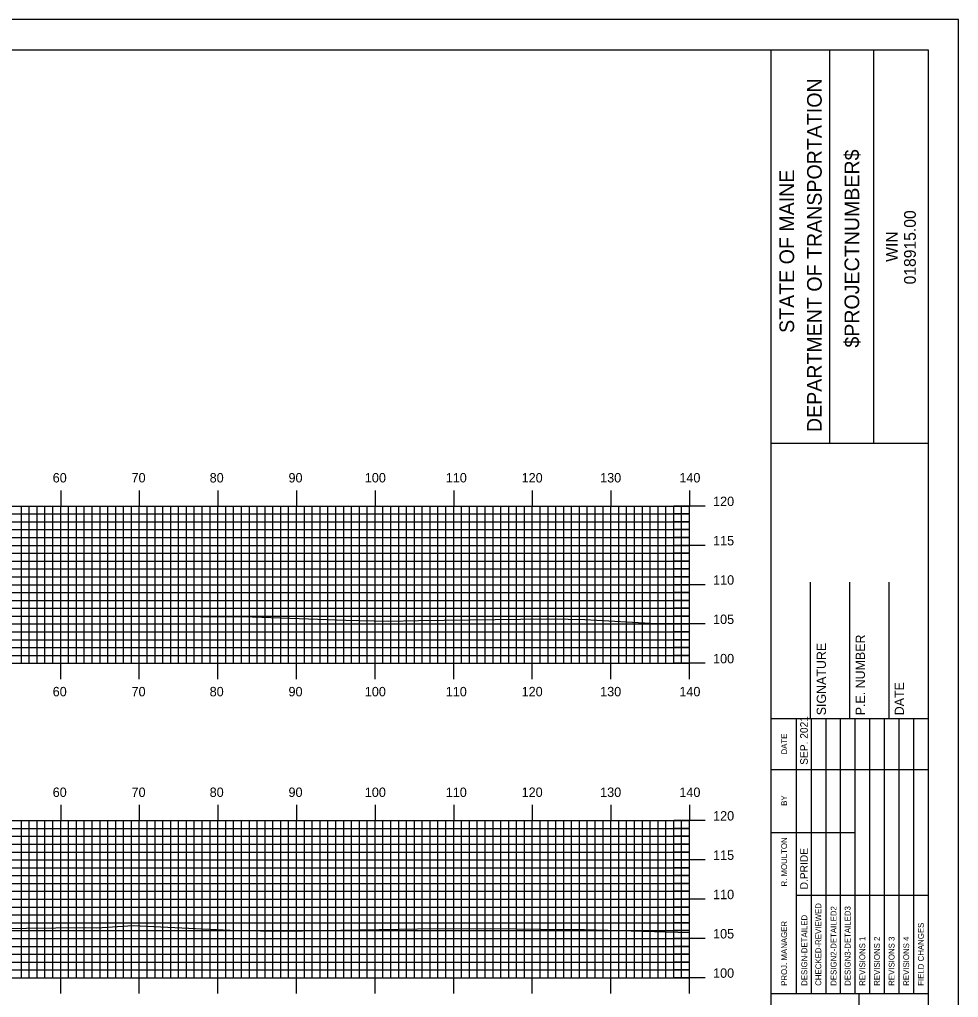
# Model space of a CAD drawing. Extents: x 1773203 to 1773546, y 442591 to 442811.
# Drawn here: x 1773423.4 to 1773542.8, y 442686.2 to 442810.5 of the extents above; entities that cross this region are included whole.
import ezdxf

# ---------------------------------------------------------------- set-up
doc = ezdxf.new("R2010")
doc.units = 0
for name, color, linetype in [('BORDER', 7, 'Continuous'), ('H_V ANNOTATION', 7, 'Continuous'), ('MAJOR', 7, 'Continuous'), ('MINOR', 7, 'Continuous'), ('PLOT BOUNDARY', 7, 'Continuous'), ('S_Roadway_Centerline', 7, 'Continuous')]:
    doc.layers.add(name, color=color, linetype=linetype)

msp = doc.modelspace()

# ---------------------------------------------------------------- linework, layer by layer
at = {"layer": 'BORDER'}
for p, q in [((1773519.03, 442596.67), (1773519.03, 442806.67)), ((1773526.49, 442756.66), (1773526.49, 442806.66)), ((1773532.08, 442756.66), (1773532.08, 442806.66)), ((1773519.03, 442756.65), (1773539.03, 442756.65)), ((1773524.03, 442721.67), (1773524.03, 442738.97)), ((1773529.03, 442721.67), (1773529.03, 442738.97)), ((1773534.03, 442721.67), (1773534.03, 442738.97)), ((1773519.03, 442721.67), (1773539.03, 442721.67)), ((1773519.03, 442686.67), (1773539.03, 442686.67)), ((1773530.21, 442616.67), (1773530.21, 442686.67))]:
    msp.add_line(p, q, dxfattribs=at)
msp.add_lwpolyline([(1773219.03, 442596.67), (1773539.03, 442596.67), (1773539.03, 442806.67), (1773219.03, 442806.67)], close=True, dxfattribs=at)
for points in [[(1773522.26, 442715.17), (1773522.26, 442721.67)], [(1773524.13, 442686.68), (1773524.13, 442721.67)], [(1773525.99, 442721.67), (1773525.99, 442686.68)], [(1773527.85, 442686.68), (1773527.85, 442721.67)], [(1773529.72, 442686.68), (1773529.72, 442721.67)], [(1773531.58, 442686.68), (1773531.58, 442721.67)], [(1773533.44, 442686.68), (1773533.44, 442721.67)], [(1773535.31, 442686.68), (1773535.31, 442721.67)], [(1773537.17, 442686.68), (1773537.17, 442721.67)], [(1773522.26, 442686.68), (1773522.26, 442720.26)], [(1773519.03, 442715.17), (1773539.03, 442715.17)], [(1773519.03, 442707.17), (1773522.26, 442707.17)], [(1773522.26, 442707.17), (1773529.72, 442707.17)], [(1773522.26, 442699.17), (1773539.03, 442699.17)]]:
    msp.add_lwpolyline(points, dxfattribs=at)
at = {"layer": 'MAJOR'}
for p, q in [((1773428.63, 442750.67), (1773428.63, 442748.67)), ((1773438.63, 442750.67), (1773438.63, 442748.67)), ((1773448.63, 442750.67), (1773448.63, 442748.67)), ((1773458.63, 442750.67), (1773458.63, 442748.67)), ((1773468.63, 442750.67), (1773468.63, 442748.67)), ((1773478.63, 442750.67), (1773478.63, 442748.67)), ((1773488.63, 442750.67), (1773488.63, 442748.67)), ((1773498.63, 442750.67), (1773498.63, 442748.67)), ((1773508.63, 442750.67), (1773508.63, 442748.67)), ((1773228.63, 442748.67), (1773508.63, 442748.67)), ((1773228.63, 442748.67), (1773508.63, 442748.67)), ((1773428.63, 442728.67), (1773428.63, 442748.67)), ((1773438.63, 442728.67), (1773438.63, 442748.67)), ((1773448.63, 442728.67), (1773448.63, 442748.67)), ((1773458.63, 442728.67), (1773458.63, 442748.67)), ((1773468.63, 442728.67), (1773468.63, 442748.67)), ((1773478.63, 442728.67), (1773478.63, 442748.67)), ((1773488.63, 442728.67), (1773488.63, 442748.67)), ((1773498.63, 442728.67), (1773498.63, 442748.67)), ((1773510.64, 442748.67), (1773506.63, 442748.67)), ((1773508.63, 442728.67), (1773508.63, 442748.67)), ((1773508.63, 442728.67), (1773508.63, 442748.67)), ((1773228.63, 442743.67), (1773508.63, 442743.67)), ((1773510.64, 442743.67), (1773506.63, 442743.67)), ((1773228.63, 442738.67), (1773508.63, 442738.67)), ((1773510.64, 442738.67), (1773506.63, 442738.67)), ((1773228.63, 442733.67), (1773508.63, 442733.67)), ((1773510.64, 442733.67), (1773506.63, 442733.67)), ((1773228.63, 442728.67), (1773508.63, 442728.67)), ((1773228.63, 442728.67), (1773508.63, 442728.67)), ((1773428.63, 442726.66), (1773428.63, 442728.67)), ((1773438.63, 442726.66), (1773438.63, 442728.67)), ((1773448.63, 442726.66), (1773448.63, 442728.67)), ((1773458.63, 442726.66), (1773458.63, 442728.67)), ((1773468.63, 442726.66), (1773468.63, 442728.67)), ((1773478.63, 442726.66), (1773478.63, 442728.67)), ((1773488.63, 442726.66), (1773488.63, 442728.67)), ((1773498.63, 442726.66), (1773498.63, 442728.67)), ((1773510.64, 442728.67), (1773506.63, 442728.67)), ((1773508.63, 442726.66), (1773508.63, 442728.67)), ((1773428.63, 442710.67), (1773428.63, 442708.67)), ((1773438.63, 442710.67), (1773438.63, 442708.67)), ((1773448.63, 442710.67), (1773448.63, 442708.67)), ((1773458.63, 442710.67), (1773458.63, 442708.67)), ((1773468.63, 442710.67), (1773468.63, 442708.67)), ((1773478.63, 442710.67), (1773478.63, 442708.67)), ((1773488.63, 442710.67), (1773488.63, 442708.67)), ((1773498.63, 442710.67), (1773498.63, 442708.67)), ((1773508.63, 442710.67), (1773508.63, 442708.67)), ((1773228.63, 442708.67), (1773508.63, 442708.67)), ((1773228.63, 442708.67), (1773508.63, 442708.67)), ((1773428.63, 442688.67), (1773428.63, 442708.67)), ((1773438.63, 442688.67), (1773438.63, 442708.67)), ((1773448.63, 442688.67), (1773448.63, 442708.67)), ((1773458.63, 442688.67), (1773458.63, 442708.67)), ((1773468.63, 442688.67), (1773468.63, 442708.67)), ((1773478.63, 442688.67), (1773478.63, 442708.67)), ((1773488.63, 442688.67), (1773488.63, 442708.67)), ((1773498.63, 442688.67), (1773498.63, 442708.67)), ((1773510.64, 442708.67), (1773506.63, 442708.67)), ((1773508.63, 442688.67), (1773508.63, 442708.67)), ((1773508.63, 442688.67), (1773508.63, 442708.67)), ((1773228.63, 442703.67), (1773508.63, 442703.67)), ((1773510.64, 442703.67), (1773506.63, 442703.67)), ((1773228.63, 442698.67), (1773508.63, 442698.67)), ((1773510.64, 442698.67), (1773506.63, 442698.67)), ((1773228.63, 442693.67), (1773508.63, 442693.67)), ((1773510.64, 442693.67), (1773506.63, 442693.67)), ((1773228.63, 442688.67), (1773508.63, 442688.67)), ((1773228.63, 442688.67), (1773508.63, 442688.67)), ((1773428.63, 442686.66), (1773428.63, 442688.67)), ((1773438.63, 442686.66), (1773438.63, 442688.67)), ((1773448.63, 442686.66), (1773448.63, 442688.67)), ((1773458.63, 442686.66), (1773458.63, 442688.67)), ((1773468.63, 442686.66), (1773468.63, 442688.67)), ((1773478.63, 442686.66), (1773478.63, 442688.67)), ((1773488.63, 442686.66), (1773488.63, 442688.67)), ((1773498.63, 442686.66), (1773498.63, 442688.67)), ((1773510.64, 442688.67), (1773506.63, 442688.67)), ((1773508.63, 442686.66), (1773508.63, 442688.67))]:
    msp.add_line(p, q, dxfattribs=at)
at = {"layer": 'MINOR'}
for p, q in [((1773423.63, 442728.67), (1773423.63, 442748.67)), ((1773424.63, 442728.67), (1773424.63, 442748.67)), ((1773425.63, 442728.67), (1773425.63, 442748.67)), ((1773426.63, 442728.67), (1773426.63, 442748.67)), ((1773427.63, 442728.67), (1773427.63, 442748.67)), ((1773429.63, 442728.67), (1773429.63, 442748.67)), ((1773430.63, 442728.67), (1773430.63, 442748.67)), ((1773431.63, 442728.67), (1773431.63, 442748.67)), ((1773432.63, 442728.67), (1773432.63, 442748.67)), ((1773433.63, 442728.67), (1773433.63, 442748.67)), ((1773434.63, 442728.67), (1773434.63, 442748.67)), ((1773435.63, 442728.67), (1773435.63, 442748.67)), ((1773436.63, 442728.67), (1773436.63, 442748.67)), ((1773437.63, 442728.67), (1773437.63, 442748.67)), ((1773439.63, 442728.67), (1773439.63, 442748.67)), ((1773440.63, 442728.67), (1773440.63, 442748.67)), ((1773441.63, 442728.67), (1773441.63, 442748.67)), ((1773442.63, 442728.67), (1773442.63, 442748.67)), ((1773443.63, 442728.67), (1773443.63, 442748.67)), ((1773444.63, 442728.67), (1773444.63, 442748.67)), ((1773445.63, 442728.67), (1773445.63, 442748.67)), ((1773446.63, 442728.67), (1773446.63, 442748.67)), ((1773447.63, 442728.67), (1773447.63, 442748.67)), ((1773449.63, 442728.67), (1773449.63, 442748.67)), ((1773450.63, 442728.67), (1773450.63, 442748.67)), ((1773451.63, 442728.67), (1773451.63, 442748.67)), ((1773452.63, 442728.67), (1773452.63, 442748.67)), ((1773453.63, 442728.67), (1773453.63, 442748.67)), ((1773454.63, 442728.67), (1773454.63, 442748.67)), ((1773455.63, 442728.67), (1773455.63, 442748.67)), ((1773456.63, 442728.67), (1773456.63, 442748.67)), ((1773457.63, 442728.67), (1773457.63, 442748.67)), ((1773459.63, 442728.67), (1773459.63, 442748.67)), ((1773460.63, 442728.67), (1773460.63, 442748.67)), ((1773461.63, 442728.67), (1773461.63, 442748.67)), ((1773462.63, 442728.67), (1773462.63, 442748.67)), ((1773463.63, 442728.67), (1773463.63, 442748.67)), ((1773464.63, 442728.67), (1773464.63, 442748.67)), ((1773465.63, 442728.67), (1773465.63, 442748.67)), ((1773466.63, 442728.67), (1773466.63, 442748.67)), ((1773467.63, 442728.67), (1773467.63, 442748.67)), ((1773469.63, 442728.67), (1773469.63, 442748.67)), ((1773470.63, 442728.67), (1773470.63, 442748.67)), ((1773471.63, 442728.67), (1773471.63, 442748.67)), ((1773472.63, 442728.67), (1773472.63, 442748.67)), ((1773473.63, 442728.67), (1773473.63, 442748.67)), ((1773474.63, 442728.67), (1773474.63, 442748.67)), ((1773475.63, 442728.67), (1773475.63, 442748.67)), ((1773476.63, 442728.67), (1773476.63, 442748.67)), ((1773477.63, 442728.67), (1773477.63, 442748.67)), ((1773479.63, 442728.67), (1773479.63, 442748.67)), ((1773480.63, 442728.67), (1773480.63, 442748.67)), ((1773481.63, 442728.67), (1773481.63, 442748.67)), ((1773482.63, 442728.67), (1773482.63, 442748.67)), ((1773483.63, 442728.67), (1773483.63, 442748.67)), ((1773484.63, 442728.67), (1773484.63, 442748.67)), ((1773485.63, 442728.67), (1773485.63, 442748.67)), ((1773486.63, 442728.67), (1773486.63, 442748.67)), ((1773487.63, 442728.67), (1773487.63, 442748.67)), ((1773489.63, 442728.67), (1773489.63, 442748.67)), ((1773490.63, 442728.67), (1773490.63, 442748.67)), ((1773491.63, 442728.67), (1773491.63, 442748.67)), ((1773492.63, 442728.67), (1773492.63, 442748.67)), ((1773493.63, 442728.67), (1773493.63, 442748.67)), ((1773494.63, 442728.67), (1773494.63, 442748.67)), ((1773495.63, 442728.67), (1773495.63, 442748.67)), ((1773496.63, 442728.67), (1773496.63, 442748.67)), ((1773497.63, 442728.67), (1773497.63, 442748.67)), ((1773499.63, 442728.67), (1773499.63, 442748.67)), ((1773500.63, 442728.67), (1773500.63, 442748.67)), ((1773501.63, 442728.67), (1773501.63, 442748.67)), ((1773502.63, 442728.67), (1773502.63, 442748.67)), ((1773503.63, 442728.67), (1773503.63, 442748.67)), ((1773504.63, 442728.67), (1773504.63, 442748.67)), ((1773505.63, 442728.67), (1773505.63, 442748.67)), ((1773506.63, 442728.67), (1773506.63, 442748.67)), ((1773507.63, 442728.67), (1773507.63, 442748.67)), ((1773228.63, 442747.67), (1773508.63, 442747.67)), ((1773508.63, 442747.67), (1773506.63, 442747.67)), ((1773228.63, 442746.67), (1773508.63, 442746.67)), ((1773228.63, 442745.67), (1773508.63, 442745.67)), ((1773508.63, 442746.67), (1773506.63, 442746.67)), ((1773508.63, 442745.67), (1773506.63, 442745.67)), ((1773228.63, 442744.67), (1773508.63, 442744.67)), ((1773508.63, 442744.67), (1773506.63, 442744.67)), ((1773228.63, 442742.67), (1773508.63, 442742.67)), ((1773508.63, 442742.67), (1773506.63, 442742.67)), ((1773228.63, 442741.67), (1773508.63, 442741.67)), ((1773228.63, 442740.67), (1773508.63, 442740.67)), ((1773508.63, 442741.67), (1773506.63, 442741.67)), ((1773508.63, 442740.67), (1773506.63, 442740.67)), ((1773228.63, 442739.67), (1773508.63, 442739.67)), ((1773508.63, 442739.67), (1773506.63, 442739.67)), ((1773228.63, 442737.67), (1773508.63, 442737.67)), ((1773508.63, 442737.67), (1773506.63, 442737.67)), ((1773228.63, 442736.67), (1773508.63, 442736.67)), ((1773228.63, 442735.67), (1773508.63, 442735.67)), ((1773508.63, 442736.67), (1773506.63, 442736.67)), ((1773508.63, 442735.67), (1773506.63, 442735.67)), ((1773228.63, 442734.67), (1773508.63, 442734.67)), ((1773508.63, 442734.67), (1773506.63, 442734.67)), ((1773228.63, 442732.67), (1773508.63, 442732.67)), ((1773508.63, 442732.67), (1773506.63, 442732.67)), ((1773228.63, 442731.67), (1773508.63, 442731.67)), ((1773228.63, 442730.67), (1773508.63, 442730.67)), ((1773508.63, 442731.67), (1773506.63, 442731.67)), ((1773508.63, 442730.67), (1773506.63, 442730.67)), ((1773228.63, 442729.67), (1773508.63, 442729.67)), ((1773508.63, 442729.67), (1773506.63, 442729.67)), ((1773423.63, 442688.67), (1773423.63, 442708.67)), ((1773424.63, 442688.67), (1773424.63, 442708.67)), ((1773425.63, 442688.67), (1773425.63, 442708.67)), ((1773426.63, 442688.67), (1773426.63, 442708.67)), ((1773427.63, 442688.67), (1773427.63, 442708.67)), ((1773429.63, 442688.67), (1773429.63, 442708.67)), ((1773430.63, 442688.67), (1773430.63, 442708.67)), ((1773431.63, 442688.67), (1773431.63, 442708.67)), ((1773432.63, 442688.67), (1773432.63, 442708.67)), ((1773433.63, 442688.67), (1773433.63, 442708.67)), ((1773434.63, 442688.67), (1773434.63, 442708.67)), ((1773435.63, 442688.67), (1773435.63, 442708.67)), ((1773436.63, 442688.67), (1773436.63, 442708.67)), ((1773437.63, 442688.67), (1773437.63, 442708.67)), ((1773439.63, 442688.67), (1773439.63, 442708.67)), ((1773440.63, 442688.67), (1773440.63, 442708.67)), ((1773441.63, 442688.67), (1773441.63, 442708.67)), ((1773442.63, 442688.67), (1773442.63, 442708.67)), ((1773443.63, 442688.67), (1773443.63, 442708.67)), ((1773444.63, 442688.67), (1773444.63, 442708.67)), ((1773445.63, 442688.67), (1773445.63, 442708.67)), ((1773446.63, 442688.67), (1773446.63, 442708.67)), ((1773447.63, 442688.67), (1773447.63, 442708.67)), ((1773449.63, 442688.67), (1773449.63, 442708.67)), ((1773450.63, 442688.67), (1773450.63, 442708.67)), ((1773451.63, 442688.67), (1773451.63, 442708.67)), ((1773452.63, 442688.67), (1773452.63, 442708.67)), ((1773453.63, 442688.67), (1773453.63, 442708.67)), ((1773454.63, 442688.67), (1773454.63, 442708.67)), ((1773455.63, 442688.67), (1773455.63, 442708.67)), ((1773456.63, 442688.67), (1773456.63, 442708.67)), ((1773457.63, 442688.67), (1773457.63, 442708.67)), ((1773459.63, 442688.67), (1773459.63, 442708.67)), ((1773460.63, 442688.67), (1773460.63, 442708.67)), ((1773461.63, 442688.67), (1773461.63, 442708.67)), ((1773462.63, 442688.67), (1773462.63, 442708.67)), ((1773463.63, 442688.67), (1773463.63, 442708.67)), ((1773464.63, 442688.67), (1773464.63, 442708.67)), ((1773465.63, 442688.67), (1773465.63, 442708.67)), ((1773466.63, 442688.67), (1773466.63, 442708.67)), ((1773467.63, 442688.67), (1773467.63, 442708.67)), ((1773469.63, 442688.67), (1773469.63, 442708.67)), ((1773470.63, 442688.67), (1773470.63, 442708.67)), ((1773471.63, 442688.67), (1773471.63, 442708.67)), ((1773472.63, 442688.67), (1773472.63, 442708.67)), ((1773473.63, 442688.67), (1773473.63, 442708.67)), ((1773474.63, 442688.67), (1773474.63, 442708.67)), ((1773475.63, 442688.67), (1773475.63, 442708.67)), ((1773476.63, 442688.67), (1773476.63, 442708.67)), ((1773477.63, 442688.67), (1773477.63, 442708.67)), ((1773479.63, 442688.67), (1773479.63, 442708.67)), ((1773480.63, 442688.67), (1773480.63, 442708.67)), ((1773481.63, 442688.67), (1773481.63, 442708.67)), ((1773482.63, 442688.67), (1773482.63, 442708.67)), ((1773483.63, 442688.67), (1773483.63, 442708.67)), ((1773484.63, 442688.67), (1773484.63, 442708.67)), ((1773485.63, 442688.67), (1773485.63, 442708.67)), ((1773486.63, 442688.67), (1773486.63, 442708.67)), ((1773487.63, 442688.67), (1773487.63, 442708.67)), ((1773489.63, 442688.67), (1773489.63, 442708.67)), ((1773490.63, 442688.67), (1773490.63, 442708.67)), ((1773491.63, 442688.67), (1773491.63, 442708.67)), ((1773492.63, 442688.67), (1773492.63, 442708.67)), ((1773493.63, 442688.67), (1773493.63, 442708.67)), ((1773494.63, 442688.67), (1773494.63, 442708.67)), ((1773495.63, 442688.67), (1773495.63, 442708.67)), ((1773496.63, 442688.67), (1773496.63, 442708.67)), ((1773497.63, 442688.67), (1773497.63, 442708.67)), ((1773499.63, 442688.67), (1773499.63, 442708.67)), ((1773500.63, 442688.67), (1773500.63, 442708.67)), ((1773501.63, 442688.67), (1773501.63, 442708.67)), ((1773502.63, 442688.67), (1773502.63, 442708.67)), ((1773503.63, 442688.67), (1773503.63, 442708.67)), ((1773504.63, 442688.67), (1773504.63, 442708.67)), ((1773505.63, 442688.67), (1773505.63, 442708.67)), ((1773506.63, 442688.67), (1773506.63, 442708.67)), ((1773507.63, 442688.67), (1773507.63, 442708.67)), ((1773228.63, 442707.67), (1773508.63, 442707.67)), ((1773508.63, 442707.67), (1773506.63, 442707.67)), ((1773228.63, 442706.67), (1773508.63, 442706.67)), ((1773508.63, 442706.67), (1773506.63, 442706.67)), ((1773228.63, 442705.67), (1773508.63, 442705.67)), ((1773228.63, 442704.67), (1773508.63, 442704.67)), ((1773508.63, 442705.67), (1773506.63, 442705.67)), ((1773508.63, 442704.67), (1773506.63, 442704.67)), ((1773228.63, 442702.67), (1773508.63, 442702.67)), ((1773508.63, 442702.67), (1773506.63, 442702.67)), ((1773228.63, 442701.67), (1773508.63, 442701.67)), ((1773508.63, 442701.67), (1773506.63, 442701.67)), ((1773228.63, 442700.67), (1773508.63, 442700.67)), ((1773228.63, 442699.67), (1773508.63, 442699.67)), ((1773508.63, 442700.67), (1773506.63, 442700.67)), ((1773508.63, 442699.67), (1773506.63, 442699.67)), ((1773228.63, 442697.67), (1773508.63, 442697.67)), ((1773508.63, 442697.67), (1773506.63, 442697.67)), ((1773228.63, 442696.67), (1773508.63, 442696.67)), ((1773508.63, 442696.67), (1773506.63, 442696.67)), ((1773228.63, 442695.67), (1773508.63, 442695.67)), ((1773228.63, 442694.67), (1773508.63, 442694.67)), ((1773508.63, 442695.67), (1773506.63, 442695.67)), ((1773508.63, 442694.67), (1773506.63, 442694.67)), ((1773228.63, 442692.67), (1773508.63, 442692.67)), ((1773508.63, 442692.67), (1773506.63, 442692.67)), ((1773228.63, 442691.67), (1773508.63, 442691.67)), ((1773508.63, 442691.67), (1773506.63, 442691.67)), ((1773228.63, 442690.67), (1773508.63, 442690.67)), ((1773228.63, 442689.67), (1773508.63, 442689.67)), ((1773508.63, 442690.67), (1773506.63, 442690.67)), ((1773508.63, 442689.67), (1773506.63, 442689.67))]:
    msp.add_line(p, q, dxfattribs=at)
at = {"layer": 'PLOT BOUNDARY'}
msp.add_lwpolyline([(1773202.85, 442590.55), (1773542.85, 442590.55), (1773542.85, 442810.55), (1773202.85, 442810.55)], close=True, dxfattribs=at)
at = {"layer": 'S_Roadway_Centerline'}
for points in [[(1773414.67, 442734.66), (1773430.96, 442734.65), (1773435.39, 442734.62), (1773439.72, 442734.68), (1773453.01, 442734.56), (1773464.89, 442734.15), (1773470.28, 442734.05), (1773474.13, 442734.12), (1773490.39, 442734.32), (1773493.19, 442734.27), (1773495.32, 442734.25), (1773504.43, 442733.72), (1773508.63, 442733.73)], [(1773420.48, 442694.95), (1773431.77, 442695.05), (1773433.22, 442695.04), (1773437.85, 442695.31), (1773451.1, 442694.68), (1773456.96, 442694.62), (1773466.68, 442694.76), (1773474.01, 442694.88), (1773483.29, 442694.96), (1773489.71, 442694.86), (1773495.27, 442694.81), (1773508.63, 442694.42)]]:
    msp.add_lwpolyline(points, dxfattribs=at)

# ---------------------------------------------------------------- texts
at = {"layer": 'BORDER'}
for s, height, p in [('DEPARTMENT OF TRANSPORTATION', 1.8635, (1773525.45, 442758.08)), ('$PROJECTNUMBER$', 1.8635, (1773530.22, 442768.82)), ('STATE OF MAINE', 1.8635, (1773521.94, 442770.69)), ('018915.00', 1.491, (1773537.42, 442776.86)), ('WIN', 1.491, (1773535.11, 442779.73)), ('P.E. NUMBER', 1.1811, (1773530.95, 442722.06)), ('SIGNATURE', 1.181, (1773525.99, 442722.06)), ('DATE', 1.181, (1773535.91, 442722.06)), ('SEP. 2021', 0.969, (1773523.68, 442715.76)), ('DATE', 0.743, (1773521.04, 442717.08)), ('BY', 0.743, (1773521.04, 442710.54)), ('R. MOULTON', 0.745, (1773521.04, 442700.28)), ('D.PRIDE', 0.969, (1773523.68, 442699.92)), ('CHECKED-REVIEWED', 0.7455, (1773525.39, 442687.65)), ('DESIGN2-DETAILED2', 0.7455, (1773527.33, 442687.65)), ('DESIGN3-DETAILED3', 0.7455, (1773529.12, 442687.65)), ('PROJ. MANAGER', 0.7455, (1773521.04, 442687.65)), ('DESIGN-DETAILED', 0.7455, (1773523.61, 442687.65)), ('FIELD CHANGES', 0.7455, (1773538.44, 442687.65)), ('REVISIONS 1', 0.7455, (1773530.98, 442687.65)), ('REVISIONS 2', 0.7455, (1773532.85, 442687.65)), ('REVISIONS 3', 0.7455, (1773534.71, 442687.65)), ('REVISIONS 4', 0.7455, (1773536.57, 442687.65))]:
    msp.add_text(s, height=height, rotation=90, dxfattribs=at).set_placement(p)
at = {"layer": 'H_V ANNOTATION'}
for s, p in [('60', (1773427.61, 442751.67)), ('70', (1773437.64, 442751.67)), ('80', (1773447.58, 442751.67)), ('90', (1773457.61, 442751.67)), ('100', (1773467.32, 442751.67)), ('110', (1773477.62, 442751.67)), ('120', (1773487.27, 442751.67)), ('130', (1773497.26, 442751.67)), ('140', (1773507.34, 442751.67)), ('120', (1773511.63, 442748.67)), ('115', (1773511.63, 442743.67)), ('110', (1773511.63, 442738.67)), ('105', (1773511.63, 442733.67)), ('100', (1773511.63, 442728.67)), ('60', (1773427.61, 442724.47)), ('70', (1773437.64, 442724.47)), ('80', (1773447.58, 442724.47)), ('90', (1773457.61, 442724.47)), ('100', (1773467.32, 442724.47)), ('110', (1773477.62, 442724.47)), ('120', (1773487.27, 442724.47)), ('130', (1773497.26, 442724.47)), ('140', (1773507.34, 442724.47)), ('60', (1773427.61, 442711.67)), ('70', (1773437.64, 442711.67)), ('80', (1773447.58, 442711.67)), ('90', (1773457.61, 442711.67)), ('100', (1773467.32, 442711.67)), ('110', (1773477.62, 442711.67)), ('120', (1773487.27, 442711.67)), ('130', (1773497.26, 442711.67)), ('140', (1773507.34, 442711.67)), ('120', (1773511.63, 442708.67)), ('115', (1773511.63, 442703.67)), ('110', (1773511.63, 442698.67)), ('105', (1773511.63, 442693.67)), ('100', (1773511.63, 442688.67))]:
    msp.add_text(s, height=1.2, dxfattribs=at).set_placement(p)

doc.saveas('drawing.dxf')
